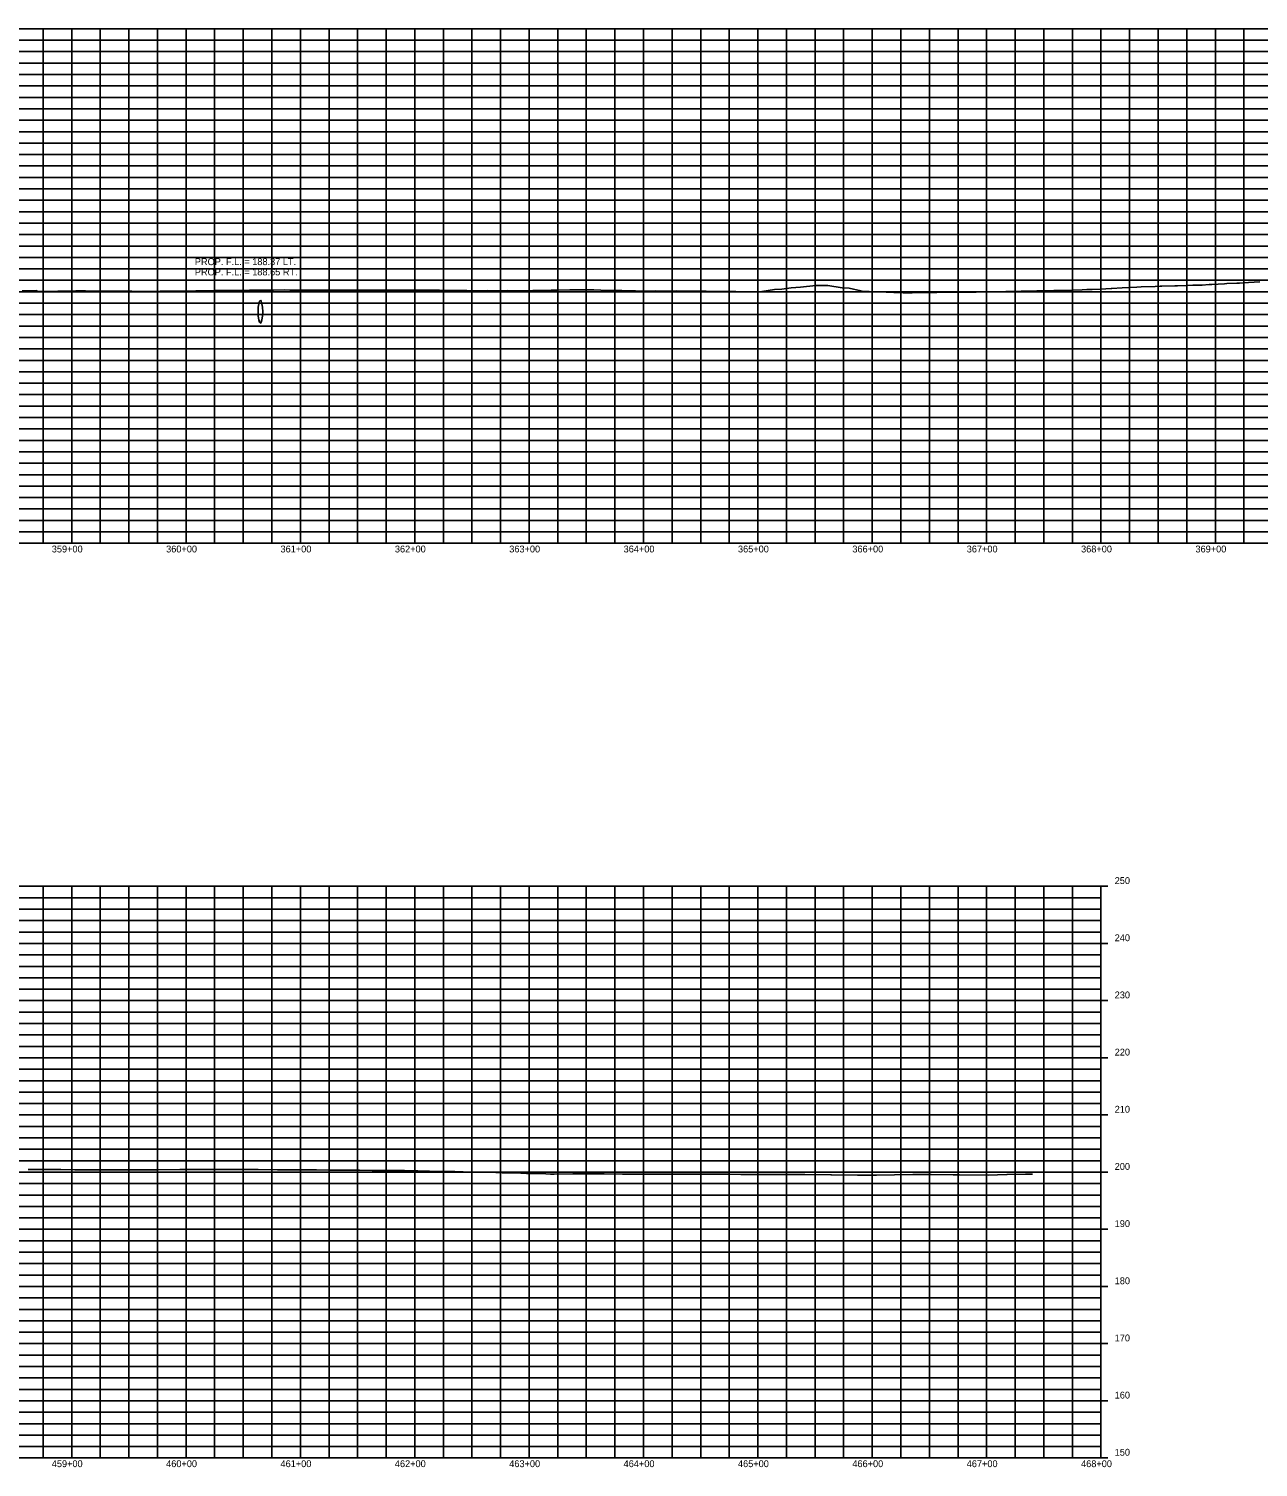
# Model space of a CAD drawing. Extents: x 1399671 to 1408349, y 1930471 to 1933387.
# Drawn here: x 1406187 to 1407262, y 1930471 to 1931729 of the extents above; entities that cross this region are included whole.
import ezdxf

# ---------------------------------------------------------------- set-up
doc = ezdxf.new("R2010")
doc.units = 0
for name, color, linetype in [('R_Drainage', 7, 'Continuous'), ('R_Exist Surface', 7, 'Continuous'), ('R_Grid', 7, 'Continuous'), ('R_Grid Annot', 7, 'Continuous'), ('R_Vert Alg Annot', 7, 'Continuous')]:
    doc.layers.add(name, color=color, linetype=linetype)

msp = doc.modelspace()

# ---------------------------------------------------------------- linework, layer by layer
at = {"layer": 'R_Drainage'}
msp.add_ellipse((1406389.2, 1931481.1), major_axis=(0, 10), ratio=0.2, dxfattribs=at)
at = {"layer": 'R_Exist Surface'}
for points in [[(1406180.9, 1931499.3), (1406193.7, 1931499.6), (1406194.1, 1931498.7), (1406201.1, 1931498.9), (1406212, 1931499), (1406219.7, 1931499.1), (1406227.8, 1931499.3), (1406236.2, 1931499.3), (1406244.1, 1931499.2), (1406252.7, 1931499.2), (1406260.5, 1931499.1), (1406268.9, 1931499), (1406276.8, 1931499), (1406285.2, 1931498.9), (1406293.2, 1931498.9), (1406301.7, 1931499.1), (1406308.1, 1931499), (1406317.4, 1931499.2), (1406323.1, 1931499.2), (1406332.9, 1931499.4), (1406338.1, 1931499.4), (1406348.4, 1931499.6), (1406353.1, 1931499.6), (1406364.1, 1931499.7), (1406369.6, 1931499.8), (1406379.8, 1931499.9), (1406386.5, 1931500.1), (1406395.6, 1931500.1), (1406400.6, 1931500.1), (1406410, 1931500.2), (1406414.9, 1931500.1), (1406426, 1931500.1), (1406431, 1931500), (1406442.1, 1931499.9), (1406447.1, 1931499.9), (1406454, 1931500), (1406465.9, 1931500), (1406477.3, 1931499.9), (1406484.6, 1931500.1), (1406495.1, 1931500.1), (1406499.8, 1931500), (1406504.1, 1931499.9), (1406515.1, 1931500), (1406519.2, 1931499.9), (1406530.5, 1931499.9), (1406534.3, 1931499.9), (1406545.9, 1931499.9), (1406551.5, 1931499.8), (1406564.2, 1931499.7), (1406569.7, 1931499.6), (1406582.5, 1931499.5), (1406587.6, 1931499.6), (1406599.7, 1931499.5), (1406605.6, 1931499.6), (1406617, 1931499.5), (1406627.3, 1931499.7), (1406633.4, 1931499.8), (1406643.5, 1931499.9), (1406649.9, 1931500), (1406659.7, 1931500.2), (1406665.4, 1931500.2), (1406675.5, 1931500.3), (1406680.9, 1931500.3), (1406693.1, 1931499.8), (1406699.2, 1931499.8), (1406705.2, 1931499.7), (1406717.3, 1931499.3), (1406723.7, 1931499.2), (1406735.1, 1931499.3), (1406741.2, 1931499.2), (1406753, 1931499.3), (1406760.5, 1931499.2), (1406769.9, 1931499.1), (1406778.9, 1931499), (1406787.2, 1931498.9), (1406798, 1931498.8), (1406804.9, 1931498.8), (1406818, 1931498.6), (1406823.2, 1931498.5), (1406827.7, 1931498.8), (1406838.6, 1931500.5), (1406845.2, 1931500.9), (1406853.3, 1931502.1), (1406861.4, 1931502.5), (1406874.8, 1931504), (1406879.9, 1931504.2), (1406885.3, 1931504), (1406897.8, 1931502), (1406904, 1931501.6), (1406914.3, 1931499.3), (1406915.3, 1931499.2), (1406921.5, 1931498.8), (1406928.3, 1931498.4), (1406936.5, 1931498.1), (1406937.1, 1931498.1), (1406943.2, 1931498), (1406951.2, 1931497.7), (1406958.1, 1931497.7), (1406959, 1931497.7), (1406969.2, 1931497.9), (1406975.1, 1931497.9), (1406980.8, 1931497.9), (1406988.3, 1931498.1), (1406993, 1931498.1), (1406998.1, 1931498.1), (1407002.7, 1931498.1), (1407010.4, 1931498.3), (1407015.2, 1931498.3), (1407024.5, 1931498.4), (1407027.8, 1931498.5), (1407032.5, 1931498.5), (1407041, 1931498.8), (1407046.4, 1931498.8), (1407046.9, 1931498.8), (1407054.3, 1931499.1), (1407060.6, 1931499.2), (1407068.2, 1931499.3), (1407068.9, 1931499.3), (1407076.2, 1931499.5), (1407083.1, 1931499.6), (1407090.1, 1931499.8), (1407091.2, 1931499.8), (1407099.5, 1931500.1), (1407107.8, 1931500.3), (1407111.9, 1931500.5), (1407116.6, 1931500.7), (1407123.9, 1931501), (1407133.1, 1931501.4), (1407133.8, 1931501.4), (1407142.8, 1931501.9), (1407149.2, 1931502.3), (1407155.6, 1931502.6), (1407159.3, 1931502.8), (1407171.5, 1931503.2), (1407175.9, 1931503.4), (1407177.5, 1931503.5), (1407188.8, 1931503.8), (1407191, 1931503.8), (1407199.3, 1931504.1), (1407204.6, 1931504.3), (1407205.4, 1931504.3), (1407212.6, 1931504.5), (1407218.9, 1931504.9), (1407219.8, 1931504.9), (1407221.2, 1931505), (1407232.2, 1931505.5), (1407234.3, 1931505.7), (1407243, 1931506.1), (1407245.2, 1931506.2), (1407248.7, 1931506.4), (1407253.1, 1931506.7), (1407263, 1931507.2)], [(1406186.3, 1930731), (1406188, 1930730.9), (1406188, 1930730.9), (1406199.9, 1930730.9), (1406201.3, 1930730.8), (1406209.8, 1930730.8), (1406213.4, 1930730.8), (1406214.6, 1930730.8), (1406227, 1930730.7), (1406227.9, 1930730.7), (1406231.6, 1930730.7), (1406240.6, 1930730.7), (1406241.1, 1930730.7), (1406253.4, 1930730.7), (1406254.9, 1930730.7), (1406255.3, 1930730.7), (1406269.3, 1930730.7), (1406269.4, 1930730.7), (1406270.7, 1930730.7), (1406275.2, 1930730.7), (1406283.5, 1930730.6), (1406283.7, 1930730.6), (1406283.9, 1930730.6), (1406297, 1930730.6), (1406298.1, 1930730.6), (1406298.8, 1930730.6), (1406318.8, 1930730.8), (1406321.3, 1930730.8), (1406340.7, 1930731), (1406341.9, 1930731), (1406344.5, 1930731), (1406362.5, 1930730.9), (1406362.8, 1930730.9), (1406365.9, 1930730.9), (1406383.4, 1930730.8), (1406384.3, 1930730.8), (1406387.3, 1930730.8), (1406404.3, 1930730.7), (1406406.1, 1930730.7), (1406409.3, 1930730.7), (1406414.9, 1930730.7), (1406427.9, 1930730.6), (1406431.1, 1930730.5), (1406438.4, 1930730.5), (1406449.7, 1930730.4), (1406453.6, 1930730.4), (1406467.1, 1930730.3), (1406471.5, 1930730.2), (1406476, 1930730.2), (1406487, 1930730.1), (1406493.4, 1930730), (1406495.3, 1930730), (1406504.8, 1930730), (1406514.6, 1930729.9), (1406515.2, 1930729.9), (1406526.9, 1930729.7), (1406536.9, 1930729.5), (1406537, 1930729.5), (1406545.8, 1930729.3), (1406558.8, 1930729.1), (1406559.2, 1930729.1), (1406566.6, 1930728.9), (1406580, 1930728.6), (1406580.6, 1930728.5), (1406595, 1930728.2), (1406600.7, 1930728), (1406602.4, 1930728), (1406617, 1930727.6), (1406621.8, 1930727.5), (1406624.2, 1930727.4), (1406638.9, 1930727), (1406642.9, 1930726.9), (1406646, 1930726.9), (1406646.2, 1930726.9), (1406662.5, 1930727), (1406664.6, 1930727), (1406667.9, 1930727), (1406682.1, 1930727.1), (1406682.8, 1930727.1), (1406689.7, 1930727), (1406705.9, 1930726.9), (1406706.5, 1930726.9), (1406707.1, 1930726.9), (1406711.5, 1930726.9), (1406730.5, 1930726.8), (1406731, 1930726.8), (1406731.9, 1930726.8), (1406733.3, 1930726.8), (1406752.1, 1930726.9), (1406752.6, 1930726.9), (1406755.1, 1930726.9), (1406773.2, 1930726.9), (1406773.4, 1930726.9), (1406776.9, 1930726.9), (1406791.2, 1930726.8), (1406791.3, 1930726.8), (1406797, 1930726.7), (1406798.7, 1930726.7), (1406809.3, 1930726.6), (1406809.4, 1930726.6), (1406818.4, 1930726.6), (1406820.6, 1930726.6), (1406823.3, 1930726.6), (1406823.3, 1930726.6), (1406837.3, 1930726.6), (1406837.4, 1930726.6), (1406842.4, 1930726.6), (1406851.3, 1930726.6), (1406864.2, 1930726.6), (1406864.9, 1930726.6), (1406865.3, 1930726.6), (1406888, 1930726.2), (1406888.5, 1930726.2), (1406911.4, 1930725.9), (1406911.7, 1930725.9), (1406927.5, 1930726), (1406927.7, 1930726), (1406927.9, 1930726), (1406943.7, 1930726.2), (1406943.8, 1930726.2), (1406959.7, 1930726.4), (1406959.7, 1930726.4), (1406975.6, 1930726.5), (1406975.7, 1930726.5), (1406994.9, 1930726.3), (1407000.5, 1930726.3), (1407000.6, 1930726.3), (1407025.5, 1930726), (1407025.5, 1930726), (1407041.9, 1930726.4), (1407041.9, 1930726.4), (1407042.3, 1930726.4), (1407058.3, 1930726.8), (1407058.3, 1930726.8), (1407064.2, 1930726.9)]]:
    msp.add_lwpolyline(points, dxfattribs=at)
at = {"layer": 'R_Grid'}
for p, q in [((1400324.2, 1931728.6), (1408324.2, 1931728.6)), ((1400324.2, 1931728.6), (1408324.2, 1931728.6)), ((1406199.2, 1931278.6), (1406199.2, 1931728.6)), ((1406224.2, 1931278.6), (1406224.2, 1931728.6)), ((1406249.2, 1931278.6), (1406249.2, 1931728.6)), ((1406274.2, 1931278.6), (1406274.2, 1931728.6)), ((1406299.2, 1931278.6), (1406299.2, 1931728.6)), ((1406324.2, 1931278.6), (1406324.2, 1931728.6)), ((1406349.2, 1931278.6), (1406349.2, 1931728.6)), ((1406374.2, 1931278.6), (1406374.2, 1931728.6)), ((1406399.2, 1931278.6), (1406399.2, 1931728.6)), ((1406424.2, 1931278.6), (1406424.2, 1931728.6)), ((1406449.2, 1931278.6), (1406449.2, 1931728.6)), ((1406474.2, 1931278.6), (1406474.2, 1931728.6)), ((1406499.2, 1931278.6), (1406499.2, 1931728.6)), ((1406524.2, 1931278.6), (1406524.2, 1931728.6)), ((1406549.2, 1931278.6), (1406549.2, 1931728.6)), ((1406574.2, 1931278.6), (1406574.2, 1931728.6)), ((1406599.2, 1931278.6), (1406599.2, 1931728.6)), ((1406624.2, 1931278.6), (1406624.2, 1931728.6)), ((1406649.2, 1931278.6), (1406649.2, 1931728.6)), ((1406674.2, 1931278.6), (1406674.2, 1931728.6)), ((1406699.2, 1931278.6), (1406699.2, 1931728.6)), ((1406724.2, 1931278.6), (1406724.2, 1931728.6)), ((1406749.2, 1931278.6), (1406749.2, 1931728.6)), ((1406774.2, 1931278.6), (1406774.2, 1931728.6)), ((1406799.2, 1931278.6), (1406799.2, 1931728.6)), ((1406824.2, 1931278.6), (1406824.2, 1931728.6)), ((1406849.2, 1931278.6), (1406849.2, 1931728.6)), ((1406874.2, 1931278.6), (1406874.2, 1931728.6)), ((1406899.2, 1931278.6), (1406899.2, 1931728.6)), ((1406924.2, 1931278.6), (1406924.2, 1931728.6)), ((1406949.2, 1931278.6), (1406949.2, 1931728.6)), ((1406974.2, 1931278.6), (1406974.2, 1931728.6)), ((1406999.2, 1931278.6), (1406999.2, 1931728.6)), ((1407024.2, 1931278.6), (1407024.2, 1931728.6)), ((1407049.2, 1931278.6), (1407049.2, 1931728.6)), ((1407074.2, 1931278.6), (1407074.2, 1931728.6)), ((1407099.2, 1931278.6), (1407099.2, 1931728.6)), ((1407124.2, 1931278.6), (1407124.2, 1931728.6)), ((1407149.2, 1931278.6), (1407149.2, 1931728.6)), ((1407174.2, 1931278.6), (1407174.2, 1931728.6)), ((1407199.2, 1931278.6), (1407199.2, 1931728.6)), ((1407224.2, 1931278.6), (1407224.2, 1931728.6)), ((1407249.2, 1931278.6), (1407249.2, 1931728.6)), ((1400324.2, 1931718.6), (1408324.2, 1931718.6)), ((1400324.2, 1931708.6), (1408324.2, 1931708.6)), ((1400324.2, 1931698.6), (1408324.2, 1931698.6)), ((1400324.2, 1931688.6), (1408324.2, 1931688.6)), ((1400324.2, 1931678.6), (1408324.2, 1931678.6)), ((1400324.2, 1931668.6), (1408324.2, 1931668.6)), ((1400324.2, 1931658.6), (1408324.2, 1931658.6)), ((1400324.2, 1931648.6), (1408324.2, 1931648.6)), ((1400324.2, 1931638.6), (1408324.2, 1931638.6)), ((1400324.2, 1931628.6), (1408324.2, 1931628.6)), ((1400324.2, 1931618.6), (1408324.2, 1931618.6)), ((1400324.2, 1931608.6), (1408324.2, 1931608.6)), ((1400324.2, 1931598.6), (1408324.2, 1931598.6)), ((1400324.2, 1931588.6), (1408324.2, 1931588.6)), ((1400324.2, 1931578.6), (1408324.2, 1931578.6)), ((1400324.2, 1931568.6), (1408324.2, 1931568.6)), ((1400324.2, 1931558.6), (1408324.2, 1931558.6)), ((1400324.2, 1931548.6), (1408324.2, 1931548.6)), ((1400324.2, 1931538.6), (1408324.2, 1931538.6)), ((1400324.2, 1931528.6), (1408324.2, 1931528.6)), ((1400324.2, 1931518.6), (1408324.2, 1931518.6)), ((1400324.2, 1931508.6), (1408324.2, 1931508.6)), ((1400324.2, 1931498.6), (1408324.2, 1931498.6)), ((1400324.2, 1931488.6), (1408324.2, 1931488.6)), ((1400324.2, 1931478.6), (1408324.2, 1931478.6)), ((1400324.2, 1931468.6), (1408324.2, 1931468.6)), ((1400324.2, 1931458.6), (1408324.2, 1931458.6)), ((1400324.2, 1931448.6), (1408324.2, 1931448.6)), ((1400324.2, 1931438.6), (1408324.2, 1931438.6)), ((1400324.2, 1931428.6), (1408324.2, 1931428.6)), ((1400324.2, 1931418.6), (1408324.2, 1931418.6)), ((1400324.2, 1931408.6), (1408324.2, 1931408.6)), ((1400324.2, 1931398.6), (1408324.2, 1931398.6)), ((1400324.2, 1931388.6), (1408324.2, 1931388.6)), ((1400324.2, 1931378.6), (1408324.2, 1931378.6)), ((1400324.2, 1931368.6), (1408324.2, 1931368.6)), ((1400324.2, 1931358.6), (1408324.2, 1931358.6)), ((1400324.2, 1931348.6), (1408324.2, 1931348.6)), ((1400324.2, 1931338.6), (1408324.2, 1931338.6)), ((1400324.2, 1931328.6), (1408324.2, 1931328.6)), ((1400324.2, 1931318.6), (1408324.2, 1931318.6)), ((1400324.2, 1931308.6), (1408324.2, 1931308.6)), ((1400324.2, 1931298.6), (1408324.2, 1931298.6)), ((1400324.2, 1931288.6), (1408324.2, 1931288.6)), ((1400324.2, 1931278.6), (1408324.2, 1931278.6)), ((1400324.2, 1930978.6), (1407124.2, 1930978.6)), ((1400324.2, 1930978.6), (1407124.2, 1930978.6)), ((1406199.2, 1930478.6), (1406199.2, 1930978.6)), ((1406224.2, 1930478.6), (1406224.2, 1930978.6)), ((1406249.2, 1930478.6), (1406249.2, 1930978.6)), ((1406274.2, 1930478.6), (1406274.2, 1930978.6)), ((1406299.2, 1930478.6), (1406299.2, 1930978.6)), ((1406324.2, 1930478.6), (1406324.2, 1930978.6)), ((1406349.2, 1930478.6), (1406349.2, 1930978.6)), ((1406374.2, 1930478.6), (1406374.2, 1930978.6)), ((1406399.2, 1930478.6), (1406399.2, 1930978.6)), ((1406424.2, 1930478.6), (1406424.2, 1930978.6)), ((1406449.2, 1930478.6), (1406449.2, 1930978.6)), ((1406474.2, 1930478.6), (1406474.2, 1930978.6)), ((1406499.2, 1930478.6), (1406499.2, 1930978.6)), ((1406524.2, 1930478.6), (1406524.2, 1930978.6)), ((1406549.2, 1930478.6), (1406549.2, 1930978.6)), ((1406574.2, 1930478.6), (1406574.2, 1930978.6)), ((1406599.2, 1930478.6), (1406599.2, 1930978.6)), ((1406624.2, 1930478.6), (1406624.2, 1930978.6)), ((1406649.2, 1930478.6), (1406649.2, 1930978.6)), ((1406674.2, 1930478.6), (1406674.2, 1930978.6)), ((1406699.2, 1930478.6), (1406699.2, 1930978.6)), ((1406724.2, 1930478.6), (1406724.2, 1930978.6)), ((1406749.2, 1930478.6), (1406749.2, 1930978.6)), ((1406774.2, 1930478.6), (1406774.2, 1930978.6)), ((1406799.2, 1930478.6), (1406799.2, 1930978.6)), ((1406824.2, 1930478.6), (1406824.2, 1930978.6)), ((1406849.2, 1930478.6), (1406849.2, 1930978.6)), ((1406874.2, 1930478.6), (1406874.2, 1930978.6)), ((1406899.2, 1930478.6), (1406899.2, 1930978.6)), ((1406924.2, 1930478.6), (1406924.2, 1930978.6)), ((1406949.2, 1930478.6), (1406949.2, 1930978.6)), ((1406974.2, 1930478.6), (1406974.2, 1930978.6)), ((1406999.2, 1930478.6), (1406999.2, 1930978.6)), ((1407024.2, 1930478.6), (1407024.2, 1930978.6)), ((1407049.2, 1930478.6), (1407049.2, 1930978.6)), ((1407074.2, 1930478.6), (1407074.2, 1930978.6)), ((1407099.2, 1930478.6), (1407099.2, 1930978.6)), ((1407124.2, 1930478.6), (1407124.2, 1930978.6)), ((1400324.2, 1930968.6), (1407124.2, 1930968.6)), ((1400324.2, 1930958.6), (1407124.2, 1930958.6)), ((1400324.2, 1930948.6), (1407124.2, 1930948.6)), ((1400324.2, 1930938.6), (1407124.2, 1930938.6)), ((1400324.2, 1930928.6), (1407124.2, 1930928.6)), ((1400324.2, 1930918.6), (1407124.2, 1930918.6)), ((1400324.2, 1930908.6), (1407124.2, 1930908.6)), ((1400324.2, 1930898.6), (1407124.2, 1930898.6)), ((1400324.2, 1930888.6), (1407124.2, 1930888.6)), ((1400324.2, 1930878.6), (1407124.2, 1930878.6)), ((1400324.2, 1930868.6), (1407124.2, 1930868.6)), ((1400324.2, 1930858.6), (1407124.2, 1930858.6)), ((1400324.2, 1930848.6), (1407124.2, 1930848.6)), ((1400324.2, 1930838.6), (1407124.2, 1930838.6)), ((1400324.2, 1930828.6), (1407124.2, 1930828.6)), ((1400324.2, 1930818.6), (1407124.2, 1930818.6)), ((1400324.2, 1930808.6), (1407124.2, 1930808.6)), ((1400324.2, 1930798.6), (1407124.2, 1930798.6)), ((1400324.2, 1930788.6), (1407124.2, 1930788.6)), ((1400324.2, 1930778.6), (1407124.2, 1930778.6)), ((1400324.2, 1930768.6), (1407124.2, 1930768.6)), ((1400324.2, 1930758.6), (1407124.2, 1930758.6)), ((1400324.2, 1930748.6), (1407124.2, 1930748.6)), ((1400324.2, 1930738.6), (1407124.2, 1930738.6)), ((1400324.2, 1930728.6), (1407124.2, 1930728.6)), ((1400324.2, 1930718.6), (1407124.2, 1930718.6)), ((1400324.2, 1930708.6), (1407124.2, 1930708.6)), ((1400324.2, 1930698.6), (1407124.2, 1930698.6)), ((1400324.2, 1930688.6), (1407124.2, 1930688.6)), ((1400324.2, 1930678.6), (1407124.2, 1930678.6)), ((1400324.2, 1930668.6), (1407124.2, 1930668.6)), ((1400324.2, 1930658.6), (1407124.2, 1930658.6)), ((1400324.2, 1930648.6), (1407124.2, 1930648.6)), ((1400324.2, 1930638.6), (1407124.2, 1930638.6)), ((1400324.2, 1930628.6), (1407124.2, 1930628.6)), ((1400324.2, 1930618.6), (1407124.2, 1930618.6)), ((1400324.2, 1930608.6), (1407124.2, 1930608.6)), ((1400324.2, 1930598.6), (1407124.2, 1930598.6)), ((1400324.2, 1930588.6), (1407124.2, 1930588.6)), ((1400324.2, 1930578.6), (1407124.2, 1930578.6)), ((1400324.2, 1930568.6), (1407124.2, 1930568.6)), ((1400324.2, 1930558.6), (1407124.2, 1930558.6)), ((1400324.2, 1930548.6), (1407124.2, 1930548.6)), ((1400324.2, 1930538.6), (1407124.2, 1930538.6)), ((1400324.2, 1930528.6), (1407124.2, 1930528.6)), ((1400324.2, 1930518.6), (1407124.2, 1930518.6)), ((1400324.2, 1930508.6), (1407124.2, 1930508.6)), ((1400324.2, 1930498.6), (1407124.2, 1930498.6)), ((1400324.2, 1930488.6), (1407124.2, 1930488.6)), ((1400324.2, 1930478.6), (1407124.2, 1930478.6))]:
    msp.add_line(p, q, dxfattribs=at)
at = {"layer": 'R_Grid Annot'}
for p, q in [((1407130.2, 1930978.6), (1407124.2, 1930978.6)), ((1407130.2, 1930978.6), (1407124.2, 1930978.6)), ((1407124.2, 1930968.6), (1407121.2, 1930968.6)), ((1407124.2, 1930958.6), (1407121.2, 1930958.6)), ((1407124.2, 1930948.6), (1407121.2, 1930948.6)), ((1407124.2, 1930938.6), (1407121.2, 1930938.6)), ((1407130.2, 1930928.6), (1407124.2, 1930928.6)), ((1407124.2, 1930918.6), (1407121.2, 1930918.6)), ((1407124.2, 1930908.6), (1407121.2, 1930908.6)), ((1407124.2, 1930898.6), (1407121.2, 1930898.6)), ((1407124.2, 1930888.6), (1407121.2, 1930888.6)), ((1407130.2, 1930878.6), (1407124.2, 1930878.6)), ((1407124.2, 1930868.6), (1407121.2, 1930868.6)), ((1407124.2, 1930858.6), (1407121.2, 1930858.6)), ((1407124.2, 1930848.6), (1407121.2, 1930848.6)), ((1407124.2, 1930838.6), (1407121.2, 1930838.6)), ((1407130.2, 1930828.6), (1407124.2, 1930828.6)), ((1407124.2, 1930818.6), (1407121.2, 1930818.6)), ((1407124.2, 1930808.6), (1407121.2, 1930808.6)), ((1407124.2, 1930798.6), (1407121.2, 1930798.6)), ((1407124.2, 1930788.6), (1407121.2, 1930788.6)), ((1407130.2, 1930778.6), (1407124.2, 1930778.6)), ((1407124.2, 1930768.6), (1407121.2, 1930768.6)), ((1407124.2, 1930758.6), (1407121.2, 1930758.6)), ((1407124.2, 1930748.6), (1407121.2, 1930748.6)), ((1407124.2, 1930738.6), (1407121.2, 1930738.6)), ((1407130.2, 1930728.6), (1407124.2, 1930728.6)), ((1407124.2, 1930718.6), (1407121.2, 1930718.6)), ((1407124.2, 1930708.6), (1407121.2, 1930708.6)), ((1407124.2, 1930698.6), (1407121.2, 1930698.6)), ((1407124.2, 1930688.6), (1407121.2, 1930688.6)), ((1407130.2, 1930678.6), (1407124.2, 1930678.6)), ((1407124.2, 1930668.6), (1407121.2, 1930668.6)), ((1407124.2, 1930658.6), (1407121.2, 1930658.6)), ((1407124.2, 1930648.6), (1407121.2, 1930648.6)), ((1407124.2, 1930638.6), (1407121.2, 1930638.6)), ((1407130.2, 1930628.6), (1407124.2, 1930628.6)), ((1407124.2, 1930618.6), (1407121.2, 1930618.6)), ((1407124.2, 1930608.6), (1407121.2, 1930608.6)), ((1407124.2, 1930598.6), (1407121.2, 1930598.6)), ((1407124.2, 1930588.6), (1407121.2, 1930588.6)), ((1407130.2, 1930578.6), (1407124.2, 1930578.6)), ((1407124.2, 1930568.6), (1407121.2, 1930568.6)), ((1407124.2, 1930558.6), (1407121.2, 1930558.6)), ((1407124.2, 1930548.6), (1407121.2, 1930548.6)), ((1407124.2, 1930538.6), (1407121.2, 1930538.6)), ((1407130.2, 1930528.6), (1407124.2, 1930528.6)), ((1407124.2, 1930518.6), (1407121.2, 1930518.6)), ((1407124.2, 1930508.6), (1407121.2, 1930508.6)), ((1407124.2, 1930498.6), (1407121.2, 1930498.6)), ((1407124.2, 1930488.6), (1407121.2, 1930488.6)), ((1407130.2, 1930478.6), (1407124.2, 1930478.6))]:
    msp.add_line(p, q, dxfattribs=at)

# ---------------------------------------------------------------- texts
for s, p in [('359+00', (1406206.8, 1931270.6)), ('360+00', (1406306.8, 1931270.6)), ('361+00', (1406406.8, 1931270.6)), ('362+00', (1406506.8, 1931270.6)), ('363+00', (1406606.8, 1931270.6)), ('364+00', (1406706.8, 1931270.6)), ('365+00', (1406806.8, 1931270.6)), ('366+00', (1406906.8, 1931270.6)), ('367+00', (1407006.8, 1931270.6)), ('368+00', (1407106.8, 1931270.6)), ('369+00', (1407206.8, 1931270.6)), ('250', (1407136.2, 1930980.6)), ('250', (1407136.2, 1930980.6)), ('240', (1407136.2, 1930930.6)), ('230', (1407136.2, 1930880.6)), ('220', (1407136.2, 1930830.6)), ('210', (1407136.2, 1930780.6)), ('200', (1407136.2, 1930730.6)), ('190', (1407136.2, 1930680.6)), ('180', (1407136.2, 1930630.6)), ('170', (1407136.2, 1930580.6)), ('160', (1407136.2, 1930530.6)), ('150', (1407136.2, 1930480.6)), ('459+00', (1406206.8, 1930470.6)), ('460+00', (1406306.8, 1930470.6)), ('461+00', (1406406.8, 1930470.6)), ('462+00', (1406506.8, 1930470.6)), ('463+00', (1406606.8, 1930470.6)), ('464+00', (1406706.8, 1930470.6)), ('465+00', (1406806.8, 1930470.6)), ('466+00', (1406906.8, 1930470.6)), ('467+00', (1407006.8, 1930470.6)), ('468+00', (1407106.8, 1930470.6))]:
    msp.add_text(s, height=6, dxfattribs=at).set_placement(p)
at = {"layer": 'R_Vert Alg Annot'}
for s, p in [('PROP. F.L. = 188.37 LT.', (1406331.9, 1931521.9)), ('PROP. F.L. = 188.65 RT.', (1406331.9, 1931512.9))]:
    msp.add_text(s, height=6, dxfattribs=at).set_placement(p)

doc.saveas('drawing.dxf')
